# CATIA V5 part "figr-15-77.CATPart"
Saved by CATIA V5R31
Part number: Part1
Bounding box of the stored display mesh (mm): x -59.264 to 75.079, y -54.323 to 58.486, z 0 to 41.762
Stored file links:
  D:\PROJECTS\Project 2021\US EDITION\CATIA V5 6R 2021\Resources\Part Files\c15_catia_v5_6r2021_prt\figr-15-77.CATPart
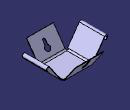
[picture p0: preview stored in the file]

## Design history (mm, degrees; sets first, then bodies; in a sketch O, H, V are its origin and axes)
SheetMetalParameters1: Thickness 1, BendRadius 5, KFactor 0.5 {= log(min(100,max(20*SheetMetalParameters1.BendRadius,SheetMetalParameters1.Thickness)/SheetMetalParameters1.Thickness))/log(100)/2}, ReliefRadialLength 1, ReliefAxialLength 2, MinimumBendRadius 0
Body1 (main body)
  Sketch1 on xy-plane, origin (0, 0, 0), H (1, 0, 0), V (0, 1, 0)
    line L1 (-24.5181, 30.1968) -> (40.3332, 30.1968)
    line L2 (40.3332, 30.1968) -> (40.3332, -26.0343)
    line L3 (40.3332, -26.0343) -> (-24.5181, -26.0343)
    line L4 (-24.5181, -26.0343) -> (-24.5181, 30.1968)
    horizontal: L1 H, L3 H
    vertical: L2 V, L4 V
  Wall1: Thickness 1, Profile Sketch1
  d_NewWallOnEdge1: NewWallOnEdge_Edge edge [face of Wall1 | face of Wall1], NewWallOnEdge_Length 40.2311, NewWallOnEdge_HeightLimitOffset 0, NewWallOnEdge_WidthOffset1 0, NewWallOnEdge_WidthOffset2 0, NewWallOnEdge_Angle 125, NewWallOnEdge_BendRadiusValue 5 {= SheetMetalParameters1.BendRadius}, NewWallOnEdge_BendTable SheetMetalParameters1, KFacteur 0.5 {= log(min(100,max(20*d_NewWallOnEdge1.Radius,SheetMetalParameters1.Thickness)/SheetMetalParameters1.Thickness))/log(100)/2}
  d_NewWallOnEdge2: NewWallOnEdge_Edge edge [face of Wall1 | face of Wall1], NewWallOnEdge_Length 40.2311, NewWallOnEdge_HeightLimitOffset 0, NewWallOnEdge_WidthOffset1 0, NewWallOnEdge_WidthOffset2 0, NewWallOnEdge_Angle 125, NewWallOnEdge_BendRadiusValue 5 {= SheetMetalParameters1.BendRadius}, NewWallOnEdge_BendTable SheetMetalParameters1, KFacteur 0.5 {= log(min(100,max(20*d_NewWallOnEdge2.Radius,SheetMetalParameters1.Thickness)/SheetMetalParameters1.Thickness))/log(100)/2}
  d_NewWallOnEdge3: NewWallOnEdge_Edge edge [face of Wall1 | face of Wall1], NewWallOnEdge_Length 40.2311, NewWallOnEdge_HeightLimitOffset 0, NewWallOnEdge_WidthOffset1 0, NewWallOnEdge_WidthOffset2 0, NewWallOnEdge_Angle 125, NewWallOnEdge_BendRadiusValue 5 {= SheetMetalParameters1.BendRadius}, NewWallOnEdge_BendTable SheetMetalParameters1, KFacteur 0.5 {= log(min(100,max(20*d_NewWallOnEdge3.Radius,SheetMetalParameters1.Thickness)/SheetMetalParameters1.Thickness))/log(100)/2}
  d_NewWallOnEdge4: NewWallOnEdge_Edge edge [face of Wall1 | face of Wall1], NewWallOnEdge_Length 40.2311, NewWallOnEdge_HeightLimitOffset 0, NewWallOnEdge_WidthOffset1 0, NewWallOnEdge_WidthOffset2 0, NewWallOnEdge_Angle 125, NewWallOnEdge_BendRadiusValue 5 {= SheetMetalParameters1.BendRadius}, NewWallOnEdge_BendTable SheetMetalParameters1, KFacteur 0.5 {= log(min(100,max(20*d_NewWallOnEdge4.Radius,SheetMetalParameters1.Thickness)/SheetMetalParameters1.Thickness))/log(100)/2}
  Sketch2 on face of d_NewWallOnEdge4, origin (0, -16.9994, -11.9031), H (-1, 0, 0), V (0, -0.5736, 0.8192)
    construction line L1 (-8.3417, 33.0355) -> (-8.3417, 47.6528)
    line L2 (-5.6402, 47.6528) -> (-5.6402, 38.4491)
    line L3 (-11.0431, 38.4491) -> (-11.0431, 47.6528)
    arc A1 centre (-8.3417, 33.0355) radius 6.0503 from (-5.6402, 38.4491) to (-11.0431, 38.4491) cw
    arc A2 centre (-8.3417, 47.6528) radius 2.7015 from (-11.0431, 47.6528) to (-5.6402, 47.6528) cw
    radius A1 = 6.0503
    radius A2 = 2.7015
    vertical: L1 V
    tangency: A2 L2, A2 L3
    parallelism: L2 L3, L2 L1
  CutOut1: Direction Sketch2, EndLimit through (limit type 3), Orientation false, Profile Sketch2, StartLimit through (limit type 2)
  Sketch3 on face of d_NewWallOnEdge2, origin (0, 19.7925, -13.8589), H (1, 0, 0), V (0, 0.5736, 0.8192)
    construction line L1 (6.0153, 41.1403) -> (6.0153, 57.8706)
    line L2 (8.7383, 57.8706) -> (8.7383, 46.3808)
    line L3 (3.2923, 46.3808) -> (3.2923, 57.8706)
    arc A1 centre (6.0153, 41.1403) radius 5.9058 from (8.7383, 46.3808) to (3.2923, 46.3808) cw
    arc A2 centre (6.0153, 57.8706) radius 2.723 from (3.2923, 57.8706) to (8.7383, 57.8706) cw
    radius A1 = 5.9058
    radius A2 = 2.723
    vertical: L1 V
    tangency: A2 L2, A2 L3
    parallelism: L2 L3, L2 L1
  CutOut2: Direction Sketch3, EndLimit through (limit type 3), Orientation true, Profile Sketch3, StartLimit through (limit type 2)
  Flange1: Angle 90, Length 5, Radius 3, KFacteur 0.444538 {= log(min(100,max(20*Flange1.Radius,SheetMetalParameters1.Thickness)/SheetMetalParameters1.Thickness))/log(100)/2}, Guide edge [face of d_NewWallOnEdge1 | face of d_NewWallOnEdge1]
  Flange2: Angle 90, Length 5, Radius 3, KFacteur 0.444538 {= log(min(100,max(20*Flange2.Radius,SheetMetalParameters1.Thickness)/SheetMetalParameters1.Thickness))/log(100)/2}, Guide edge [face of d_NewWallOnEdge3 | face of d_NewWallOnEdge3]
